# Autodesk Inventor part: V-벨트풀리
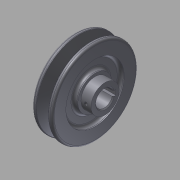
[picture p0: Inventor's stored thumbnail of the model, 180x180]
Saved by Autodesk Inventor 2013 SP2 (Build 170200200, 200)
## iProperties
Company: 한국ATC센터
Created: 2014-07
Part Number: V-벨트풀리
Document SubType Name: Modeling
Designer: KYOUNG IL JANG
Density: 7.87 g/cm^3
Material: 강철, 탄소
Mass: 1497.56 g
Surface Area: 466.268 cm^2
Volume: 190.529 cm^3
Author: KYOUNG IL JANG
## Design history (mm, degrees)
sketch "스케치1"
  geometry: L1 (-15, 0)-(15, 0); L2 (-15, 0)-(-15, 17); L3 (-15, 17)-(-11, 17); L4 (-11, 17)-(-11, 29); L5 (-11, 29)-(-15, 29); L6 (-15, 29)-(-15, 42.5); L7 (-15, 42.5)-(-10.976, 42.5); L8 (-10.976, 42.5)-(-7.154, 30); L9 (-7.154, 30)-(-2.846, 30); L10 (-2.846, 30)-(0.976, 42.5); L11 (0.976, 42.5)-(5, 42.5); L12 (5, 42.5)-(5, 29); L13 (5, 29)-(1, 29); L14 (1, 29)-(1, 17); L15 (1, 17)-(5, 17); L16 (5, 17)-(5, 14); L17 (5, 14)-(15, 14); L18 (15, 14)-(15, 0); L19 (-9.6, 38)-(-0.4, 38); 2 further points
  constraints: 38 end point, 11 parallel, 7 collinear, 3 equal length, 3 perpendicular, 2 point on line, 1 coincident, 1 horizontal, 1 midpoint
  dimensions: "d0" = 30 distance of L1.start L1.end; "d1" = 4.5 distance between parallel lines of L7 L19; "d2" = 8 distance between parallel lines of L9 L19; "d3" = 9.2 distance of L19.start L19.end; "d4" = 34 deg angle of L10 L8; "d5" = 20 distance between parallel lines of L12 L6; "d6" = 76 diameter of L19 L1; "d7" = 4 distance of L2.end L3.end; "d8" = 34 diameter of L3 L1; "d9" = 58 diameter of L5 L1; "d10" = 28 diameter of L17 L1
revolve "회전1" sketch "스케치1" stored, may be unused: angle "d11" = 90 deg
sketch "스케치2"
  geometry: L1 (-2.5, 8.124)-(-2.5, 10.8); L2 (-2.5, 10.8)-(2.5, 10.8); L3 (2.5, 10.8)-(2.5, 8.124); A1 r 8.5 centre (0, 0) between (-2.5, 8.124) and (2.5, 8.124); 1 further point
  constraints: 6 end point, 2 parallel, 2 point on circle, 1 centre point, 1 coincident, 1 horizontal, 1 vertical
  dimensions: "d12" = 17 diameter of A1; "d13" = 5 distance of L1.end L2.end; "d14" = 19.3 dimension on A1 L2 (computed from d12)
extrude "돌출1" cut sketch "스케치2" stored distance "d15" = 10; taper "d16" = 0 deg
chamfer "모따기1" distance "d17" = 1; stored, may be unused: second distance "d18" = 2, angle "d19" = 45 deg
node "작업 평면1"
sketch "스케치3"
  geometry: L1 (5, -14)-(5, 14) reference; 3 further points
  constraints: 1 horizontal alignment, 1 midpoint
  dimensions: "d20" = 5 distance from line of L1 point (0, 0)
hole "구멍1" sketch "스케치3" at (0, 0) diameter "d21" = 3.242; stored, may be unused: countersink angle "d25" = 90 deg, drill point angle "d27" = 118 deg; dims "d22" = 6, "d23" = 4, "d24" = 2, "d26" = 8
fillet "모깎기1" dims "d28" = 3, "d29" = 2, "d30" = 0.5, "d31" = 1
node "솔리드1"
